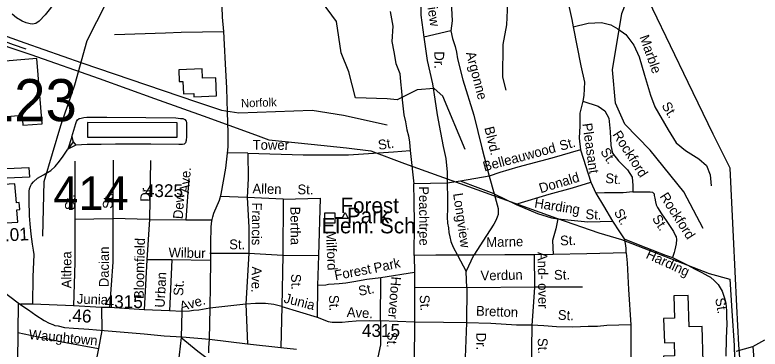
# Model space of a CAD drawing. Extents: x 1547597 to 1699558, y 810033 to 920809.
# Drawn here: x 1637363 to 1644617, y 846278 to 849529 of the extents above; entities that cross this region are included whole.
import ezdxf

# ---------------------------------------------------------------- set-up
doc = ezdxf.new("R2010")
doc.units = 0
for name, color, linetype in [('Exist Cultural Educational Facility High CELL', 7, 'Continuous'), ('Exist Cultural Educational Facility High Label', 7, 'Continuous'), ('Exist Cultural Warehouse Building Footprint', 7, 'Continuous'), ('Exist Hydrographic Creek Single Shore', 7, 'Continuous'), ('Exist Railroad Mainline Label', 7, 'Continuous'), ('Exist Railroad Siding', 7, 'Continuous'), ('Exist Road Non-System Type 51', 7, 'Continuous'), ('Exist Road Non-System Type 51 Label', 7, 'Continuous'), ('Exist Road Secondary Mileage Hundredths English Label', 7, 'Continuous'), ('Exist Road Secondary Structure Standard Bridge Number Label', 7, 'Continuous'), ('Exist Road Secondary Type 51 Attributed', 7, 'Continuous'), ('Exist Road Secondary Type 51 Label', 7, 'Continuous'), ('Exist Road Secondary Type 51 Number Label', 7, 'Continuous'), ('Exist Road Secondary Type 51 Undivided 4 Lane Attributed', 7, 'Continuous'), ('Exist Utilities Electrical Transmission Line', 7, 'Continuous')]:
    doc.layers.add(name, color=color, linetype=linetype)

msp = doc.modelspace()

# ---------------------------------------------------------------- linework, layer by layer
at = {"layer": 'Exist Cultural Educational Facility High CELL'}
msp.add_lwpolyline([(1640379.2, 847604.4), (1640477.1, 847604.4), (1640477.1, 847558.4), (1640552.2, 847558.4), (1640576.4, 847605.4), (1640605.6, 847548.8), (1640477.1, 847548.8), (1640477.1, 847502.7), (1640379.2, 847502.7)], close=True, dxfattribs=at)
at = {"layer": 'Exist Cultural Warehouse Building Footprint'}
for points in [[(1637626.6, 848470.8), (1637577.6, 849103.9), (1637148.1, 849070.6), (1637161.8, 848894.4), (1637029.7, 848884.1), (1637064.7, 848432.3), (1637218, 848444.1), (1637210.9, 848535.7), (1637432.5, 848552.8), (1637439.9, 848456.4)], [(1639105.2, 848732), (1639324.5, 848740.6), (1639317.6, 848917.4), (1639189.4, 848912.4), (1639185.8, 849004.1), (1638958.6, 848995.3), (1638963, 848880.3), (1638998.2, 848881.7), (1639002.9, 848760.4), (1639104, 848764.3)], [(1638069.7, 848340.7), (1638942.3, 848340.7), (1638942.3, 848478.7), (1638069.7, 848482.2)], [(1637136.9, 848028.8), (1637498.7, 848046), (1637503.6, 847950.6), (1637139.4, 847935.9)], [(1637391.3, 847512.5), (1637382.1, 847632.8), (1637410.3, 847634.9), (1637403.5, 847703.3), (1637376.6, 847700.9), (1637361.9, 847884.3), (1637252, 847879.4), (1637274.9, 847505.7)], [(1643678.6, 846139.8), (1644062.9, 846152.8), (1644051.3, 846498.1), (1643927.5, 846494), (1643917.2, 846799.5), (1643775.5, 846794.7), (1643782.8, 846578.3), (1643677.1, 846574.8), (1643685.1, 846337), (1643780.1, 846340.2), (1643784.4, 846213), (1643676.3, 846209.4)]]:
    msp.add_lwpolyline(points, close=True, dxfattribs=at)
at = {"layer": 'Exist Hydrographic Creek Single Shore'}
for points in [[(1642144, 848796.3), (1642113, 848925), (1642116, 849240.1), (1642152, 849433), (1642164, 849721.7), (1642149, 849866.4), (1642092, 850008.7), (1641977, 850175.2), (1641721, 850344.5), (1641574, 850554.3), (1641509, 850739.5), (1641505, 851080.9), (1641433, 851325.2), (1641450.9, 851449.7), (1641554, 851713.5), (1641581, 851863.9), (1641578, 852280.8), (1641641, 852689.9)], [(1644062.1, 847450.9), (1643875.1, 847809.2), (1643546.1, 848213.1), (1643299, 848467.6), (1643210, 848669.6), (1643180.1, 848995.2), (1643270.1, 849541.6), (1643425, 849942.2), (1643665, 850479), (1643700.1, 850606.3), (1643703, 850888.5), (1643612, 851573.2)], [(1637633.9, 847377.9), (1637649, 847909.4), (1637809.3, 848452.7), (1637947.3, 848850.3), (1638064.9, 849279.6), (1638441.6, 850024.2)], [(1641746, 848220.1), (1641527, 848739.9), (1641444, 848813.8), (1641277, 848800.8), (1641085, 848702.9), (1640985, 848711.6), (1640677.7, 848723.3), (1640612, 848975.2), (1640540, 849160.5), (1640492.9, 849466.7), (1640247, 849803.2)]]:
    msp.add_lwpolyline(points, dxfattribs=at)
at = {"layer": 'Exist Railroad Siding'}
msp.add_lwpolyline([(1637023.2, 849445.5), (1637156, 849364), (1637458.2, 849256.8), (1638013.2, 849061.6), (1638642.2, 848847.8), (1639130.7, 848682.6), (1639372.9, 848603.3), (1639541.2, 848577.9), (1640254.8, 848603.7), (1640562.2, 848552.6), (1640986.5, 848458.3)], dxfattribs=at)
at = {"layer": 'Exist Road Non-System Type 51'}
for p, q in [((1641607.4, 849373.3), (1641343, 849312.2)), ((1637916.1, 848343.2), (1637878.2, 848221.7)), ((1637916.1, 848343.2), (1637931.3, 848292.9)), ((1637931.3, 848292.9), (1637878.2, 848221.7)), ((1637954.9, 848262.6), (1637878.2, 848221.7)), ((1637931.3, 848292.9), (1637954.9, 848262.6)), ((1639631.4, 848183.6), (1639427.3, 848186.6)), ((1637946.3, 848106.7), (1637945.7, 847542.8)), ((1638318.3, 848116.9), (1638315.5, 847547.1)), ((1638684, 848113.3), (1638673.2, 847539.6)), ((1641979.2, 847960.5), (1641699.1, 847912.1)), ((1641979.2, 847960.5), (1642027.6, 847789.8)), ((1639057.3, 847937.6), (1639027, 847534)), ((1641571.8, 847891.7), (1641246, 847884.1)), ((1641699.1, 847912.1), (1641571.8, 847891.7)), ((1642967.5, 847903), (1643018.8, 847794)), ((1639622.1, 847752.2), (1639363.3, 847761)), ((1639974.3, 847737.7), (1639622.1, 847752.2)), ((1639974.3, 847737.7), (1639971.2, 847190.1)), ((1637945.7, 847542.8), (1638315.5, 847547.1)), ((1638673.2, 847539.6), (1638315.5, 847547.1)), ((1638673.2, 847539.6), (1638647.3, 847147)), ((1638673.2, 847539.6), (1639027, 847534)), ((1639027, 847534), (1639274.2, 847534.8)), ((1638647.3, 847147), (1638621.1, 846661.1)), ((1638890.5, 847147), (1638647.3, 847147)), ((1638890.5, 847147), (1638867.4, 846648.8)), ((1639263.1, 847139.3), (1638890.5, 847147)), ((1639260, 847211), (1639638.4, 847209.9)), ((1639638.4, 847209.9), (1639609.4, 846713.5)), ((1639638.4, 847209.9), (1639971.2, 847190.1)), ((1639971.2, 847190.1), (1639960, 846692.9)), ((1639971.2, 847190.1), (1640319.1, 847187.1)), ((1640319.1, 847187.1), (1640309.3, 846895.2)), ((1641248.5, 847188.6), (1641251.1, 847023.1)), ((1641830.3, 847191.6), (1641671.1, 847191.2)), ((1641671.1, 847191.2), (1641755.1, 847034)), ((1641755.1, 847034), (1641830.3, 847191.6)), ((1642418, 847195.1), (1642420.9, 846878.8)), ((1641251.1, 847023.1), (1640925.7, 846972.6)), ((1641251.1, 847023.1), (1641251.9, 846540.6)), ((1641760.4, 846874.1), (1641755.1, 847034)), ((1640920.7, 846553.1), (1640925.7, 846972.6)), ((1640309.3, 846895.2), (1640304.3, 846588)), ((1641760.4, 846874.1), (1641251.3, 846876.5)), ((1641760.4, 846874.1), (1641758, 846533.5)), ((1642420.9, 846878.8), (1641760.4, 846874.1)), ((1637394.8, 846729), (1637391.3, 846437.9)), ((1637535.9, 846713.9), (1637415.6, 846713.9)), ((1637931.5, 846698.1), (1637535.9, 846713.9)), ((1639609.4, 846713.5), (1639261.5, 846676.5)), ((1639609.4, 846713.5), (1639628.1, 846328.4)), ((1638205.5, 846682.7), (1637931.5, 846698.1)), ((1638282.5, 846682.7), (1638205.5, 846682.7)), ((1638205.5, 846682.7), (1638208.6, 846457.7)), ((1638621.1, 846661.1), (1638282.5, 846682.7)), ((1638867.4, 846648.8), (1638621.1, 846661.1)), ((1638987.5, 846642.6), (1638867.4, 846648.8)), ((1638987.5, 846642.6), (1638979.8, 846391)), ((1639960, 846692.9), (1639952.7, 846293.5)), ((1639960, 846692.9), (1640304.3, 846588)), ((1641251.9, 846540.6), (1640920.7, 846553.1)), ((1641251.9, 846540.6), (1641249.4, 846153.6)), ((1641758, 846533.5), (1641743.2, 846110.1)), ((1637391.3, 846437.9), (1637387.9, 846155.8)), ((1638208.6, 846457.7), (1638174.7, 846283)), ((1638174.7, 846283), (1638123.3, 846021.7))]:
    msp.add_line(p, q, dxfattribs=at)
for points in [[(1641010.1, 851440.3), (1641145.6, 851329.4), (1641238, 851221.6), (1641290.3, 851027.5), (1641324.2, 850531.4), (1641339.6, 850374.3), (1641404.2, 850263.3), (1641520.9, 850126.1), (1641576.4, 850036.7), (1641594.8, 849901.2), (1641619.5, 849472.9), (1641607.4, 849373.3)], [(1636915.3, 850439.1), (1636925.7, 850351.2), (1636941.4, 850206.8), (1636952.3, 850074.7), (1636960.3, 849864.7), (1636967.7, 849710.4), (1636969.8, 849576.5), (1636970.8, 849514.5), (1636977.9, 849473.7), (1636991.5, 849430.2), (1637002.2, 849405.6), (1637020.8, 849375.8), (1637038.5, 849361.4), (1637064.2, 849345.1), (1637113.8, 849326.3), (1637211.3, 849288.9), (1637346.5, 849242.7), (1637467.8, 849199)], [(1637849.6, 849892.3), (1637822.4, 849851.6), (1637809.7, 849809.9), (1637802, 849751.7), (1637769.2, 849692.3), (1637709.8, 849595.3), (1637658.4, 849529.1), (1637599.8, 849468.9), (1637567.5, 849447.3), (1637535.4, 849440), (1637511.4, 849442.2), (1637471.5, 849450.9), (1637431.9, 849467.5), (1637376.5, 849502.2), (1637335, 849536.9)], [(1642720.9, 849762.4), (1642785.5, 849483.7), (1642797.8, 849412.8)], [(1641310.4, 849739.1), (1641315.3, 849527.9), (1641343, 849312.2)], [(1641015.9, 849563.7), (1641041.4, 849419.4), (1641032.1, 849269.1), (1641050.6, 849171.2), (1641072.1, 849057.2), (1641109.1, 848958.6), (1641115.2, 848878.5), (1641124.5, 848786), (1641132.1, 848702.1), (1641139.4, 848645.9), (1641147.9, 848558.1), (1641164.9, 848487.7), (1641176.8, 848410.2), (1641193.6, 848353.1), (1641204.6, 848290.9), (1641210.8, 848211.3)], [(1642797.8, 849412.8), (1642943.8, 849447.7), (1643073.1, 849453.9), (1643162.4, 849432.3), (1643233.2, 849392.3), (1643310.2, 849339.9), (1643387.2, 849235.1), (1643439.5, 849121.1), (1643491.8, 848942.4), (1643550.3, 848748.3), (1643593.4, 848634.3), (1643722.8, 848412.5), (1643799.7, 848283.1), (1643889, 848209.1), (1644021.4, 848129), (1644095.3, 848065.3), (1644129.1, 847972.9), (1644140.5, 847865.8)], [(1642797.8, 849412.8), (1642871.7, 849033.8), (1642908.6, 848873.6), (1642900.3, 848746.3), (1642890.6, 848688.6)], [(1638331.8, 849339.3), (1638828.8, 849354.2), (1638981.9, 849362.5), (1639396.7, 849367.5)], [(1641607.4, 849373.3), (1641622.8, 849299.4), (1641647.1, 849220.7), (1641662.3, 849166.5), (1641671.8, 849100.8), (1641724.5, 848898), (1641829, 848553.8), (1641909.1, 848237.5), (1641979.2, 847960.5)], [(1641343, 849312.2), (1641376.9, 849084.2), (1641426.2, 848859.3), (1641450.3, 848710.9), (1641472.4, 848556.4), (1641505.7, 848386), (1641530.4, 848249.8), (1641558.1, 848132.8), (1641571.8, 847998.7), (1641571.8, 847891.7)], [(1642890.6, 848688.6), (1642861.8, 848573.2), (1642861.8, 848451.3), (1642855.4, 848329.5), (1642868.2, 848217.3)], [(1642890.6, 848688.6), (1643040.9, 848641.3), (1643105.6, 848595.1), (1643145.6, 848524.2), (1643157.9, 848394.8), (1643164.1, 848259.2), (1643179.5, 848185.3), (1643238, 848108.3), (1643327.3, 848022), (1643370.4, 847951.1), (1643376.5, 847871), (1643377.7, 847806.5)], [(1637916.1, 848343.2), (1637954.1, 848472.5), (1637962.3, 848492.4), (1637972.7, 848508.2), (1637986.7, 848520.1), (1638006.8, 848523.7), (1638033, 848531.4), (1638063.1, 848535), (1638256.9, 848533.8), (1638638.7, 848530.1), (1638930.4, 848527.5), (1638974.3, 848522.8), (1638998.3, 848520.4), (1639018.1, 848512.1), (1639029.8, 848495.9), (1639031.7, 848483.9), (1639033.1, 848443.8), (1639033.5, 848345.9), (1639028.9, 848306), (1639022.7, 848284.1), (1639010.4, 848272.2), (1638994.3, 848268.5), (1638958.3, 848269), (1638686.6, 848271.3), (1638342.6, 848270.5), (1638200.7, 848268.8), (1638064.8, 848266.8), (1637954.9, 848262.6)], [(1637535.9, 846713.9), (1637539.4, 846980.3), (1637550.5, 847199), (1637542.5, 847240.8), (1637534.1, 847297.2), (1637521.6, 847395.3), (1637511.1, 847495.6), (1637506.2, 847573.5), (1637500.7, 847725.7), (1637500.2, 847815.6), (1637504.4, 847835.5), (1637512.9, 847861.4), (1637523.1, 847881.4), (1637543.4, 847905), (1637583.9, 847940.4), (1637640.4, 847973.4), (1637711.1, 848016.4), (1637753.7, 848053.8), (1637796.4, 848105.1), (1637833.2, 848154.4), (1637878.2, 848221.7)], [(1639631.4, 848183.6), (1639633, 847937.5), (1639622.1, 847752.2)], [(1639631.4, 848183.6), (1640170.2, 848168.2), (1640610.4, 848168.2), (1641047.6, 848195.9), (1641210.8, 848211.3)], [(1641210.8, 848211.3), (1641246, 847884.1)], [(1642868.2, 848217.3), (1642587.8, 848136.7), (1642258.6, 848047.9), (1642083.9, 847996.8), (1641979.2, 847960.5)], [(1642868.2, 848217.3), (1642967.5, 847903)], [(1641248.5, 847188.6), (1641251.1, 847499.4), (1641248.5, 847718.5), (1641246, 847884.1)], [(1641571.8, 847891.7), (1641574.4, 847741.4), (1641574.4, 847647.2), (1641569.3, 847560.6), (1641574.4, 847502), (1641582, 847456.1), (1641587.1, 847412.8), (1641594.8, 847369.5), (1641607.5, 847323.7), (1641627.9, 847270.2), (1641671.1, 847191.2)], [(1642027.6, 847789.8), (1641873.5, 847848.2), (1641699.1, 847912.1)], [(1642260.8, 847693.9), (1642562.2, 847785), (1642791, 847845.4), (1642967.5, 847903)], [(1643377.7, 847806.5), (1643282.5, 847798), (1643210.6, 847798), (1643100.6, 847798), (1643018.8, 847794)], [(1643377.7, 847806.5), (1643491.9, 847808.6), (1643546.9, 847806.5), (1643568, 847804.4), (1643584.9, 847789.6), (1643587.1, 847772.6), (1643591.3, 847747.2), (1643597.6, 847711.3), (1643606.1, 847681.6), (1643616.7, 847654.1), (1643656.9, 847594.9), (1643701.3, 847529.3), (1643735.1, 847480.6), (1643775.3, 847423.4), (1643792.2, 847381.1), (1643798.6, 847368.4), (1643802.8, 847343), (1643800.7, 847302.8), (1643794.3, 847271.1), (1643785.9, 847243.6), (1643781.6, 847218.2), (1643764.7, 847169.5)], [(1639622.1, 847752.2), (1639638.5, 847464), (1639638.4, 847209.9)], [(1639974.3, 847737.7), (1640334.5, 847746.9), (1640319.1, 847187.1)], [(1642027.6, 847789.8), (1642065.8, 847647.2), (1642068.3, 847616.6), (1642065.8, 847586), (1642058.1, 847560.6), (1642045.4, 847530), (1642025, 847494.3), (1641953.7, 847382.3), (1641830.3, 847191.6)], [(1642027.6, 847789.8), (1642240.9, 847683.5)], [(1643018.8, 847794), (1643092.5, 847672.1), (1643179.1, 847521)], [(1642240.9, 847683.5), (1642450.9, 847596.6), (1642585.4, 847554.6), (1642647, 847546.2)], [(1637945.7, 847542.8), (1637947.1, 847122.7), (1637931.5, 846698.1)], [(1638315.5, 847547.1), (1638317, 847125), (1638282.5, 846682.7)], [(1642647, 847546.2), (1642627.4, 847448.1), (1642596.6, 847333.2), (1642602.2, 847198.7)], [(1642647, 847546.2), (1642938.3, 847515.4), (1643179.1, 847521)], [(1643179.1, 847521), (1643248, 847417.4), (1643294.6, 847351.3)], [(1643294.6, 847351.3), (1643445.4, 847290.1), (1643562.7, 847243), (1643694.9, 847192.8), (1643764.7, 847169.5)], [(1643294.6, 847351.3), (1643304.2, 847304.5), (1643311.3, 847259.8), (1643311.3, 847215.1)], [(1643313.6, 847215.1), (1642928.6, 847205.7), (1642602.2, 847198.7)], [(1643313.6, 847215.1), (1643323, 847116.3), (1643334.8, 846857.6), (1643357, 846514.4)], [(1641671.1, 847191.2), (1641459.8, 847191.2), (1641248.5, 847188.6)], [(1642418, 847195.1), (1642132.4, 847195.1), (1641830.3, 847191.6)], [(1642602.2, 847198.7), (1642418, 847195.1)], [(1643764.7, 847169.5), (1643906.2, 847097.5), (1643983.6, 847056.3), (1644048.9, 847023.2), (1644108.3, 846990.4), (1644132.3, 846976), (1644171.5, 846941.3), (1644207, 846904.7), (1644228.4, 846874.5), (1644246, 846842.1), (1644261.1, 846801.8), (1644274.6, 846763.7), (1644281.9, 846721.5), (1644287.4, 846687.4), (1644290.7, 846649.5), (1644289.8, 846589.5), (1644292.7, 846525.4), (1644286.4, 846381.4), (1644283.5, 846207.6)], [(1640925.7, 846972.6), (1640787.6, 846955.6), (1640661.3, 846931.5), (1640583.2, 846920.7), (1640519.2, 846911.8), (1640471.1, 846908.6), (1640416.6, 846905.2), (1640389.2, 846900.2), (1640309.3, 846895.2)], [(1642420.9, 846878.8), (1642408.5, 846687.4), (1642395.7, 846511)], [(1642888.7, 846878.8), (1642822.8, 846878.8), (1642761.7, 846878.8), (1642639.5, 846881.1), (1642420.9, 846878.8)], [(1639960, 846692.9), (1639884.6, 846710.5), (1639801.5, 846722.8), (1639706, 846722.8), (1639609.4, 846713.5)], [(1639261.5, 846676.5), (1639153.8, 846658), (1639101.4, 846651.9), (1639061.4, 846645.7), (1638987.5, 846642.6)], [(1640304.3, 846588), (1640411.6, 846545.6), (1640451.6, 846538.1), (1640509, 846540.6), (1640548.9, 846540.6), (1640611.3, 846545.6), (1640686.1, 846553.1), (1640818.4, 846555.6), (1640920.7, 846553.1)], [(1640920.7, 846553.1), (1640922.5, 846413.3), (1640920, 846318.4), (1640895.8, 846198.5)], [(1641758, 846533.5), (1641534.5, 846535.6), (1641251.9, 846540.6)], [(1642395.7, 846511), (1642245.1, 846511), (1641995.1, 846527), (1641758, 846533.5)], [(1642395.7, 846511), (1642392.3, 846280.2), (1642389.2, 846031.2)], [(1643357, 846514.4), (1643125.2, 846508.1), (1643035.1, 846499), (1642943.9, 846497.9), (1642795.2, 846490.3), (1642636, 846495), (1642510.7, 846504.2), (1642395.7, 846511)], [(1643357, 846514.4), (1643359.5, 846290.4), (1643360.3, 846096.3)], [(1637391.3, 846437.9), (1637823.7, 846347.7), (1638174.7, 846283)], [(1638979.8, 846391), (1638952.1, 846138.4), (1638931.3, 845879.3)], [(1638979.8, 846391), (1639143, 846258.4), (1639221.3, 846200.1), (1639265.9, 846166.7)], [(1644544.5, 846303.1), (1644564.8, 846047), (1644599.6, 845848.4), (1644623.2, 845700), (1644630.4, 845652.1), (1644631.9, 845626), (1644633.3, 845588)]]:
    msp.add_lwpolyline(points, dxfattribs=at)
at = {"layer": 'Exist Road Secondary Type 51 Attributed'}
for points in [[(1637110.3, 846951.3), (1637220.2, 846861.4), (1637394.8, 846729), (1637440.6, 846695.5), (1637495.3, 846660.2), (1637567.6, 846607.3), (1637648.7, 846554.4), (1637694.6, 846531.4), (1637731.6, 846517.3), (1637752.8, 846508.5), (1637782.7, 846503.2), (1637846.2, 846487.3), (1637932.6, 846480.2), (1638083, 846472.8), (1638232.6, 846458.6), (1638619.9, 846426.5), (1638815.7, 846407.5), (1638989.3, 846396.8), (1639256.3, 846372.8)], [(1639249, 846241), (1639251.3, 846289.3), (1639256.3, 846372.8)], [(1639256.3, 846372.8), (1639628.1, 846328.4), (1639952.7, 846293.5), (1640104.7, 846275.9)], [(1644382.3, 846256), (1644544.5, 846303.1), (1644661.9, 846367.4)]]:
    msp.add_lwpolyline(points, dxfattribs=at)
at = {"layer": 'Exist Road Secondary Type 51 Undivided 4 Lane Attributed'}
msp.add_lwpolyline([(1639256.3, 846372.8), (1639263.6, 846674.3), (1639266.6, 846903.5), (1639269.2, 847132.6), (1639271.4, 847311.8), (1639273.9, 847461.7), (1639276.5, 847503.9), (1639282.6, 847537.5), (1639287.7, 847563.3), (1639300.2, 847599.5), (1639353.6, 847727), (1639370.9, 847785.6), (1639414.8, 848038.8), (1639433.7, 848183.6), (1639437.2, 848247.3), (1639438.9, 848383.4), (1639432.8, 848584.1), (1639424.5, 848816.1), (1639413.4, 849053.4), (1639402.3, 849240), (1639396.7, 849367.5), (1639382.8, 849507.4), (1639377.2, 849713.5)], dxfattribs=at)
at = {"layer": 'Exist Utilities Electrical Transmission Line'}
for points in [[(1644714.3, 845822.4), (1644427.6, 846062.2), (1644408.8, 846320.3), (1644391.7, 846696.7), (1644358.3, 847369.1), (1644324.9, 848039.7), (1644159.3, 848369.9), (1643915.8, 848871.1), (1643571.1, 849583.7), (1643296.9, 850181.4), (1643065.1, 850652.3), (1643002.8, 850789.3), (1642843, 851105.3), (1642687.3, 851429.4), (1642531.6, 851765.4), (1642338.8, 852161.9), (1642140.4, 852580.5), (1642003.9, 852858.5), (1641908.2, 852873.6)], [(1637061.4, 849295.1), (1637519.2, 849145.1), (1638183.7, 848910.5), (1638720.9, 848715.7), (1639240.2, 848531), (1639731.4, 848352.6), (1639834.9, 848315.3), (1640246, 848270.1), (1640589.5, 848235.5), (1640828.9, 848206.4), (1641155.1, 848084.3), (1641614.6, 847918.3), (1642635.3, 847551.2), (1643045.3, 847410), (1643266.2, 847343.1), (1644121.3, 847012.1), (1644320.6, 846959.4), (1644342.5, 846649.2), (1644364.2, 846311), (1644368.7, 846184.9), (1644380.7, 846036.7), (1644606.2, 845851.9), (1644906.9, 845610)]]:
    msp.add_lwpolyline(points, dxfattribs=at)

# ---------------------------------------------------------------- texts
at = {"layer": 'Exist Cultural Educational Facility High Label'}
for s, p in [('Forest', (1640531.9, 847601.2)), ('Park', (1640594.8, 847502.5)), ('Elem. Sch.', (1640348.5, 847403.8))]:
    msp.add_text(s, height=150, dxfattribs=at).set_placement(p)
at = {"layer": 'Exist Railroad Mainline Label'}
msp.add_text('Norfolk', height=82.02, rotation=2.01182, dxfattribs=at).set_placement((1639565, 848628.3))
at = {"layer": 'Exist Road Non-System Type 51 Label'}
for s, rotation, p in [('Longview', 278.0681, (1641331, 849943.9)), ('Marble', 289.54926, (1643441.5, 849315.1)), ('Dr.', 269.87603, (1641446.6, 849174.6)), ('Argonne', 284.63937, (1641751.9, 849160)), ('St.', 301.27768, (1643654.5, 848647.3)), ('Pleasant', 278.09233, (1642886, 848470.4)), ('Blvd.', 283.42241, (1641931.7, 848431.2)), ('Rockford', 302.72611, (1643176.3, 848365.4)), ('Tower', 359.64054, (1639677.1, 848217.9)), ('St.', 8.28184, (1640905, 848215.9)), ('St.', 15.53221, (1642677.9, 848207.3)), ('Belleauwood', 15.09085, (1641933, 848006)), ('St.', 302.72611, (1643058, 848199.5)), ('Ave.', 85.71938, (1639057.8, 847791.7)), ('Donald', 16.82218, (1642481, 847793.7)), ('St.', 355.21196, (1643106.8, 847894.9)), ('Dr.', 88.91621, (1638678.4, 847710.6)), ('Allen', 358.77122, (1639674.5, 847792.1)), ('St.', 359.41635, (1640112.6, 847784.3)), ('Dew', 85.71938, (1638995.5, 847539.7)), ('Peachtree', 270.35585, (1641296.3, 847862)), ('Rockford', 302.72611, (1643635.8, 847763.6)), ('St.', 89.93399, (1637946.2, 847630.1)), ('St.', 89.72126, (1638313.8, 847642.1)), ('Longview', 278.0681, (1641627.9, 847789.7)), ('Harding', 351.09468, (1642414.9, 847655.6)), ('Francis', 269.47797, (1639671.6, 847704.6)), ('Bertha', 270.36001, (1640044.5, 847664.1)), ('St.', 357.91952, (1642915.4, 847543.3)), ('St.', 299.5267, (1643190.9, 847610.5)), ('St.', 302.72611, (1643561.5, 847548.8)), ('Milford', 272.27632, (1640391.1, 847422.6)), ('Marne', 1.37596, (1641952.1, 847269.9)), ('St.', 2.28226, (1642671.2, 847285.3)), ('Bloomfield', 88.91621, (1638616.9, 846764.8)), ('St.', 359.72829, (1639448.8, 847249.3)), ('Althea', 89.93399, (1637912.2, 846868.7)), ('Dacian', 89.72126, (1638276.1, 846879.7)), ('Wilbur', 358.7256, (1638857.5, 847171)), ('And- over', 270.74491, (1642451.2, 847222.5)), ('Harding', 335.32262, (1643497.7, 847166.6)), ('Park', 12.38774, (1640866.5, 847018.6)), ('Ave.', 268.59484, (1639670.5, 847081.6)), ('Forest', 10.77596, (1640482.3, 846947.6)), ('Urban', 86.88149, (1638818.9, 846678.8)), ('St.', 271.06252, (1640051.1, 847008.8)), ('Verdun', 1.32, (1641896.8, 846944.6)), ('St.', 1.41926, (1642611.7, 846951.6)), ('St.', 86.88149, (1639000, 846793.1)), ('Hoover', 265.43324, (1641027.7, 846986.4)), ('St.', 10.77596, (1640715.2, 846795)), ('Junia', 358.32115, (1637964, 846719.9)), ('Junia', 345.46824, (1639974.1, 846732.1)), ('St.', 271.96791, (1640420, 846802.6)), ('St.', 273.84687, (1641301.6, 846801.6)), ('Ave.', 16.24834, (1638981.7, 846644.8)), ('St.', 279.80397, (1644178.9, 846768.8)), ('Ave.', 356.68844, (1640591.3, 846591.8)), ('Bretton', 357.80908, (1641849.7, 846603.5)), ('St.', 357.40273, (1642646.7, 846564)), ('St.', 266.82771, (1640990.7, 846447.1)), ('Dr.', 269.87603, (1641854.6, 846437.2)), ('St.', 271.30301, (1642452, 846385.1))]:
    msp.add_text(s, height=95, rotation=rotation, dxfattribs=at).set_placement(p)
at = {"layer": 'Exist Road Secondary Mileage Hundredths English Label'}
for s, rotation, p in [('.01', 3.02738, (1637268.6, 847325)), ('.46', 357.1813, (1637873.4, 846545.7))]:
    msp.add_text(s, height=125, rotation=rotation, dxfattribs=at).set_placement(p)
at = {"layer": 'Exist Road Secondary Structure Standard Bridge Number Label'}
for s, height, p in [('123', 410.1, (1637050.4, 848494.7)), ('414', 328.08, (1637737, 847630))]:
    msp.add_text(s, height=height, dxfattribs=at).set_placement(p)
at = {"layer": 'Exist Road Secondary Type 51 Label'}
msp.add_text('Waughtown', height=95, rotation=354.73448, dxfattribs=at).set_placement((1637494.7, 846374.5))
at = {"layer": 'Exist Road Secondary Type 51 Number Label'}
for s, p in [('4325', (1638627, 847756.4)), ('4315', (1638236.1, 846677.1)), ('4315', (1640740.1, 846395.9))]:
    msp.add_text(s, height=125, dxfattribs=at).set_placement(p)

doc.saveas('drawing.dxf')
